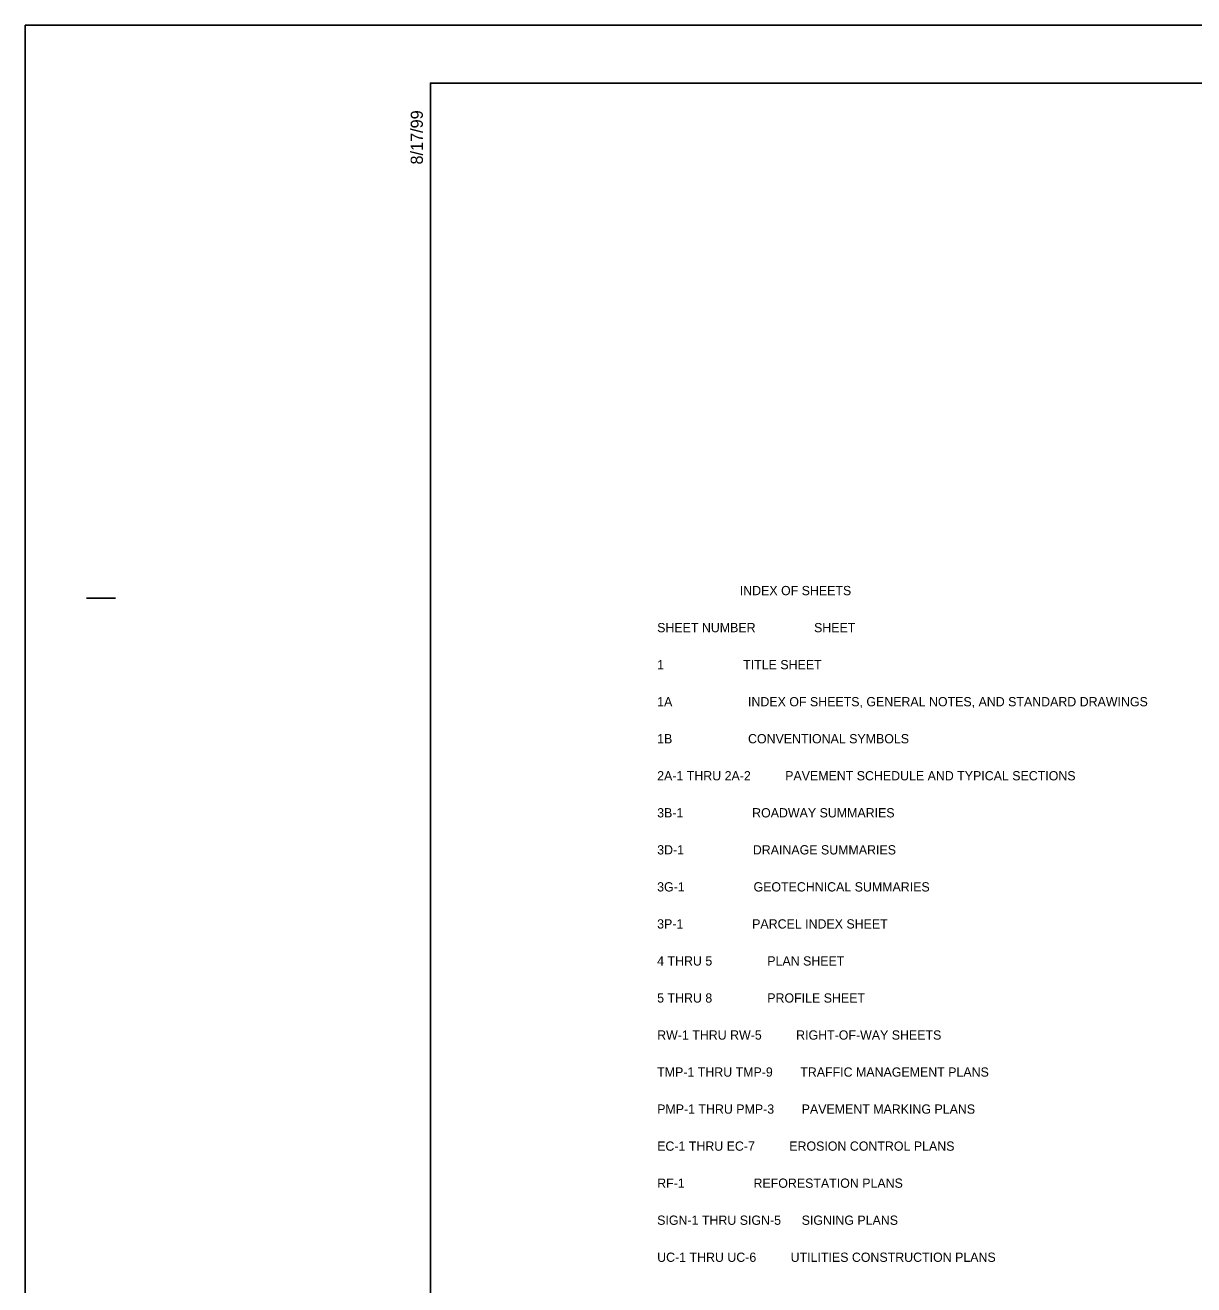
# Model space of a CAD drawing. Extents: x 885343.6 to 885383.5, y 651350.8 to 651372.8.
# Drawn here: x 885343.6 to 885353.69, y 651361.88 to 651372.76 of the extents above; entities that cross this region are included whole.
import ezdxf

# ---------------------------------------------------------------- set-up
doc = ezdxf.new("R2010")
doc.units = 0
for name, color, linetype in [('Sheet Data Text CELL', 7, 'Continuous'), ('Sheet Plan CELL', 7, 'Continuous'), ('Stewart Plot Border Xerox6279 and LJ5000', 7, 'Continuous')]:
    doc.layers.add(name, color=color, linetype=linetype)

msp = doc.modelspace()

# ---------------------------------------------------------------- linework, layer by layer
at = {"layer": 'Sheet Plan CELL'}
for p, q in [((885347.098, 651372.262), (885347.098, 651372.262)), ((885344.128, 651367.812), (885344.378, 651367.812))]:
    msp.add_line(p, q, dxfattribs=at)
msp.add_lwpolyline([(885377.098, 651372.262), (885347.098, 651372.262), (885347.098, 651351.262), (885377.098, 651351.262)], close=True, dxfattribs=at)
at = {"layer": 'Stewart Plot Border Xerox6279 and LJ5000'}
msp.add_lwpolyline([(885343.598, 651372.762), (885377.598, 651372.762), (885377.598, 651350.762), (885343.598, 651350.762)], close=True, dxfattribs=at)

# ---------------------------------------------------------------- texts
at = {"layer": 'Sheet Data Text CELL'}
for s, p in [('                        INDEX OF SHEETS ', (885349.057, 651367.837)), ('SHEET NUMBER                 SHEET   ', (885349.057, 651367.517)), ('1                       TITLE SHEET', (885349.057, 651367.197)), ('1A                      INDEX OF SHEETS, GENERAL NOTES, AND STANDARD DRAWINGS', (885349.057, 651366.877)), ('1B                      CONVENTIONAL SYMBOLS ', (885349.057, 651366.557)), ('2A-1 THRU 2A-2          PAVEMENT SCHEDULE AND TYPICAL SECTIONS', (885349.057, 651366.237)), ('3B-1                    ROADWAY SUMMARIES', (885349.057, 651365.917)), ('3D-1                    DRAINAGE SUMMARIES', (885349.057, 651365.597)), ('3G-1                    GEOTECHNICAL SUMMARIES', (885349.057, 651365.277)), ('3P-1                    PARCEL INDEX SHEET', (885349.057, 651364.957)), ('4 THRU 5                PLAN SHEET', (885349.057, 651364.637)), ('5 THRU 8                PROFILE SHEET', (885349.057, 651364.317)), ('RW-1 THRU RW-5          RIGHT-OF-WAY SHEETS', (885349.057, 651363.997)), ('TMP-1 THRU TMP-9        TRAFFIC MANAGEMENT PLANS', (885349.057, 651363.677)), ('PMP-1 THRU PMP-3        PAVEMENT MARKING PLANS', (885349.057, 651363.357)), ('EC-1 THRU EC-7          EROSION CONTROL PLANS', (885349.057, 651363.037)), ('RF-1                    REFORESTATION PLANS', (885349.057, 651362.717)), ('SIGN-1 THRU SIGN-5      SIGNING PLANS', (885349.057, 651362.397)), ('UC-1 THRU UC-6          UTILITIES CONSTRUCTION PLANS', (885349.057, 651362.077))]:
    msp.add_text(s, height=0.08, dxfattribs=at).set_placement(p)
at = {"layer": 'Sheet Plan CELL'}
msp.add_text('8/17/99', height=0.105, rotation=90, dxfattribs=at).set_placement((885347.033, 651371.558))

doc.saveas('drawing.dxf')
